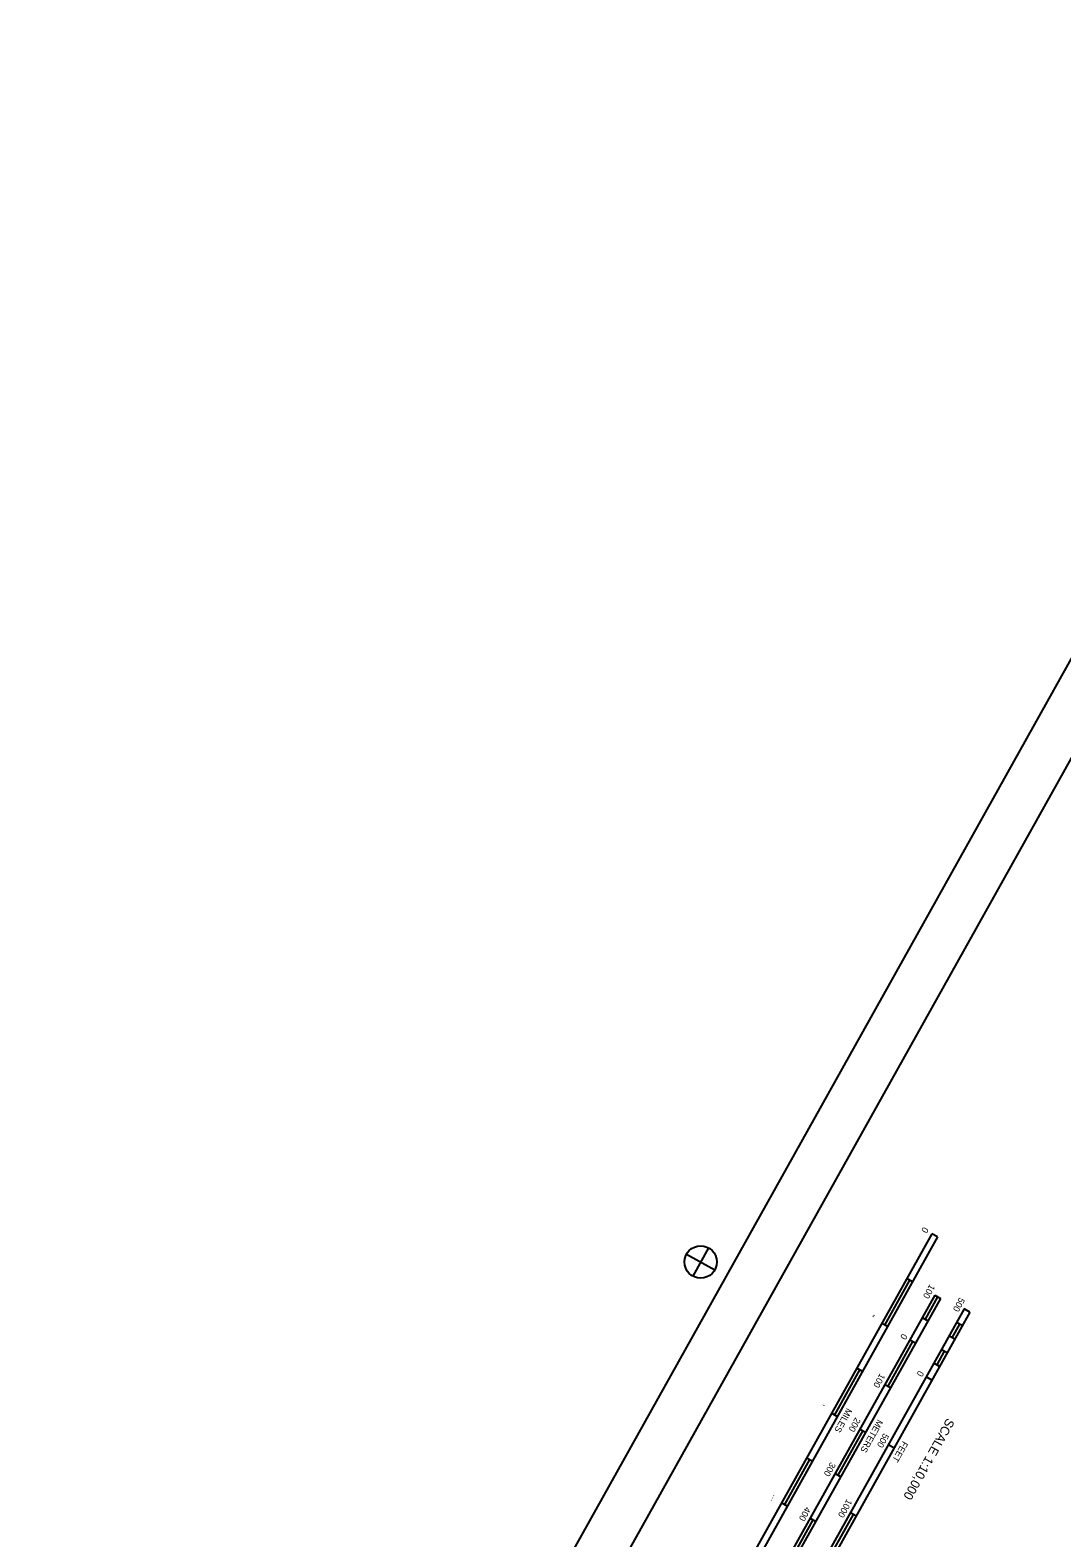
# Model space of a CAD drawing. Extents: x 3923531 to 3943530, y 207391 to 229799.
# Drawn here: x 3923785 to 3930412, y 219861 to 229544 of the extents above; entities that cross this region are included whole.
import ezdxf

# ---------------------------------------------------------------- set-up
doc = ezdxf.new("R2010")
doc.units = 0
for name, color, linetype in [('G-ANNO-NPLT', 7, 'Continuous'), ('V-ANNO-DIMS', 7, 'Continuous'), ('V-ANNO-SYMB', 7, 'Continuous')]:
    doc.layers.add(name, color=color, linetype=linetype)

msp = doc.modelspace()

# ---------------------------------------------------------------- linework, layer by layer
at = {"layer": 'G-ANNO-NPLT'}
msp.add_lwpolyline([(3932726.7, 229544.3), (3923785.3, 213539.2), (3934334.2, 207646), (3943275.5, 223651.2)], close=True, dxfattribs=at)
at = {"layer": 'V-ANNO-DIMS'}
for p, q in [((3928001.4, 221684), (3928183.2, 221582.4)), ((3928143.1, 221724.1), (3928041.5, 221542.3))]:
    msp.add_line(p, q, dxfattribs=at)
msp.add_circle((3928092.3, 221633.2), 104.2, dxfattribs=at)
at = {"layer": 'V-ANNO-SYMB'}
for p, q in [((3929577.7, 221814.2), (3928290.1, 219509.5)), ((3929613.9, 221794), (3928326.3, 219489.3)), ((3929613.9, 221794), (3929577.7, 221814.2)), ((3929434.8, 221516), (3929273.9, 221227.9)), ((3929452.9, 221505.9), (3929416.7, 221526.1)), ((3929595.7, 221419.3), (3928635.9, 219701.2)), ((3929631.9, 221399), (3928672.1, 219681)), ((3929613.8, 221409.2), (3929533.8, 221266)), ((3929595.7, 221419.3), (3929631.9, 221399)), ((3929785.3, 221331.7), (3928809.9, 219585.6)), ((3929821.6, 221311.4), (3928846.2, 219565.4)), ((3929515.7, 221276.1), (3929551.9, 221255.9)), ((3929821.6, 221311.4), (3929785.3, 221331.7)), ((3929292, 221217.8), (3929255.8, 221238)), ((3929754.7, 221234.2), (3929705.9, 221146.9)), ((3929772.8, 221224.1), (3929736.6, 221244.4)), ((3929453.8, 221122.8), (3929293.8, 220836.5)), ((3929435.7, 221132.9), (3929471.9, 221112.7)), ((3929675.3, 221049.5), (3929639, 221069.8)), ((3929724, 221136.8), (3929687.8, 221157.1)), ((3929626.5, 220962.2), (3929590.3, 220982.5)), ((3929657.1, 221059.6), (3929608.4, 220972.3)), ((3929112.9, 220939.8), (3928952, 220651.7)), ((3929131.1, 220929.7), (3929094.8, 220950)), ((3929577.7, 220874.9), (3929541.5, 220895.2)), ((3929275.7, 220846.6), (3929312, 220826.4)), ((3928933.9, 220661.9), (3928970.1, 220641.6)), ((3929133.9, 220550.1), (3928973.9, 220263.8)), ((3929115.8, 220560.2), (3929152, 220540)), ((3929333.9, 220438.4), (3929297.6, 220458.6)), ((3928791.1, 220363.6), (3928630.1, 220075.6)), ((3928809.2, 220353.5), (3928772.9, 220373.8)), ((3928955.8, 220273.9), (3928992, 220253.7)), ((3928648.2, 220065.4), (3928612, 220085.7)), ((3929071.9, 220012), (3928828, 219575.5)), ((3929090, 220001.9), (3929053.8, 220022.1)), ((3928813.9, 219977.4), (3928654, 219691.1)), ((3928795.8, 219987.6), (3928832.1, 219967.3))]:
    msp.add_line(p, q, dxfattribs=at)
msp.add_lwpolyline([(3932328.9, 228191.4), (3924261.4, 213750.5), (3934264.5, 208162.2), (3942332, 222603.1), (3932328.9, 228191.4)], dxfattribs=at)

# ---------------------------------------------------------------- texts
for s, height, p in [('0', 41.5, (3929522.8, 221861.1)), ('100', 41.5, (3929564.3, 221493.1)), ('500', 41.5, (3929755.9, 221408.9)), ('„', 38.9, (3929207.5, 221294.1)), ('0', 41.5, (3929387.3, 221176.3)), ('100', 41.5, (3929244.4, 220920.4)), ('0', 41.5, (3929493.1, 220938.5)), ('‚', 38.9, (3928885.6, 220717.9)), ('MILES', 41.5, (3929031.5, 220697.9)), ('200', 41.5, (3929086.4, 220637.5)), ('METERS', 41.5, (3929229.5, 220625.1)), ('SCALE 1:10,000', 58.35, (3929675.4, 220633.9)), ('500', 41.5, (3929268.2, 220535.9)), ('FEET', 41.5, (3929390.5, 220486.1)), ('300', 41.5, (3928926.4, 220351.2)), ('…', 38.9, (3928563.8, 220141.7)), ('1000', 41.5, (3929032.3, 220113.7)), ('400', 41.5, (3928766.4, 220064.8))]:
    msp.add_text(s, height=height, rotation=240.80991, dxfattribs=at).set_placement(p)

doc.saveas('drawing.dxf')
